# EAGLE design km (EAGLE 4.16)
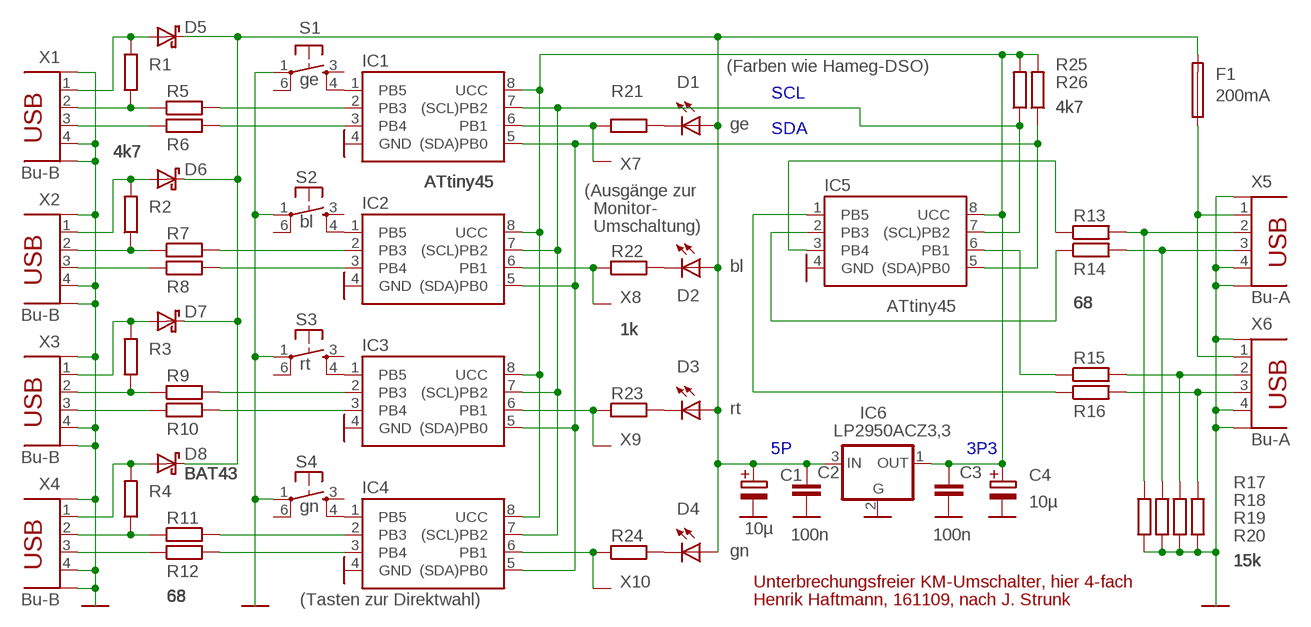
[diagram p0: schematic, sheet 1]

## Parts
C1  10µ  EE2,5-5  [E2,5-5]
C2  100n  C0805  [0805]
C3  100n  C0805  [0805]
C4  10µ  EE2,5-5  [E2,5-5]
D1  ge  LED3MM  [LED3MM]
D2  bl  LED3MM  [LED3MM]
D3  rt  LED3MM  [LED3MM]
D4  gn  LED3MM  [LED3MM]
D5  BAT43  DS  [MINIMELF]
D6  BAT43  DS  [MINIMELF]
D7  BAT43  DS  [MINIMELF]
D8  BAT43  DS  [MINIMELF]
F1  200mA  FUSE  [TE5]
IC1  ATtiny45  TN45P  [DIL08]
IC2  ATtiny45  TN45P  [DIL08]
IC3  ATtiny45  TN45P  [DIL08]
IC4  ATtiny45  TN45P  [DIL08]
IC5  ATtiny45  TN45P  [DIL08]
IC6  LP2950ACZ3,3  [TO92]
R1  4k7  R1206  [1206]
R2  4k7  R1206  [1206]
R3  4k7  R1206  [1206]
R4  4k7  R1206  [1206]
R5  68  R0805  [0805]
R6  68  R0805  [0805]
R7  68  R0805  [0805]
R8  68  R0805  [0805]
R9  68  R0805  [0805]
R10  68  R0805  [0805]
R11  68  R0805  [0805]
R12  68  R0805  [0805]
R13  68  R0805  [0805]
R14  68  R0805  [0805]
R15  68  R0805  [0805]
R16  68  R0805  [0805]
R17  15k  R0805  [0805]
R18  15k  R0805  [0805]
R19  15k  R0805  [0805]
R20  15k  R0805  [0805]
R21  1k  R0805  [0805]
R22  1k  R0805  [0805]
R23  1k  R0805  [0805]
R24  1k  R0805  [0805]
R25  4k7  R0805  [0805]
R26  4k7  R0805  [0805]
S1  ge  TASTER  [TME1]
S2  bl  TASTER  [TME1]
S3  rt  TASTER  [TME1]
S4  gn  TASTER  [TME1]
X1  Bu-B  USBB  [USBB]
X2  Bu-B  USBB  [USBB]
X3  Bu-B  USBB  [USBB]
X4  Bu-B  USBB  [USBB]
X5  Bu-A  USBA  [USBA]
X6  Bu-A  USBA  [USBA]
X7  PAD  [SMD-2MM]
X8  PAD  [SMD-2MM]
X9  PAD  [SMD-2MM]
X10  PAD  [SMD-2MM]

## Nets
3P3: C3.1 C4.+ IC1.8(UCC) IC2.8(UCC) IC3.8(UCC) IC4.8(UCC) IC5.8(UCC) IC6.1(OUT) R25.2 R26.2
5P: C1.+ C2.1 D1.A D2.A D3.A D4.A D5.K D6.K D7.K D8.K F1.2 IC6.3(IN)
5P1: D5.A R1.2 X1.1(UCC)
5P2: D6.A R2.2 X2.1(UCC)
5P3: D7.A R3.2 X3.1(UCC)
5P4: D8.A R4.2 X4.1(UCC)
5PF: F1.1 X5.1(UCC) X6.1(UCC)
GND: C1.- C2.2 C3.2 C4.- IC1.4(GND) IC2.4(GND) IC3.4(GND) IC4.4(GND) IC5.4(GND) IC6.2(GND) R17.1 R18.1 R19.1 R20.1 S1.1(P) S2.1(P) S3.1(P) S4.1(P) X1.4(GND) X1.S1(S) X1.S2(S) X2.4(GND) X2.S1(S) X2.S2(S) X3.4(GND) X3.S1(S) X3.S2(S) X4.4(GND) X4.S1(S) X4.S2(S) X5.4(GND) X5.S1(S) X5.S2(S) X6.4(GND) X6.S1(S) X6.S2(S)
N$1: D1.K R21.2
N$2: IC1.1(PB5) S1.4(S)
N$3: D2.K R22.2
N$4: D3.K R23.2
N$5: D4.K R24.2
N$6: IC2.1(PB5) S2.4(S)
N$7: IC3.1(PB5) S3.4(S)
N$8: IC4.1(PB5) S4.4(S)
N$9: R1.1 R5.1 X1.2(D-)
N$10: R6.1 X1.3(D+)
N$11: R2.1 R7.1 X2.2(D-)
N$12: IC5.3(PB4) R13.1
N$13: R8.1 X2.3(D+)
N$14: IC5.2(PB3) R14.1
N$15: IC1.2(PB3) R5.2
N$16: R3.1 R9.1 X3.2(D-)
N$17: R10.1 X3.3(D+)
N$19: R4.1 R11.1 X4.2(D-)
N$20: R12.1 X4.3(D+)
N$21: IC4.2(PB3) R11.2
N$22: IC4.3(PB4) R12.2
N$23: IC3.3(PB4) R10.2
N$24: IC1.3(PB4) R6.2
N$25: IC2.2(PB3) R7.2
N$26: IC2.3(PB4) R8.2
N$27: IC3.2(PB3) R9.2
N$29: IC1.6(PB1) R21.1 X7.1
N$30: IC2.6(PB1) R22.1 X8.1
N$31: IC3.6(PB1) R23.1 X9.1
N$32: IC4.6(PB1) R24.1 X10.1
N$33: R13.2 R17.2 X5.2(D-)
N$34: R14.2 R18.2 X5.3(D+)
N$35: R15.2 R19.2 X6.2(D-)
N$36: R16.2 R20.2 X6.3(D+)
N$37: IC5.1(PB5) R16.1
N$38: IC5.6(PB1) R15.1
SCL: IC1.7((SCL)PB2) IC2.7((SCL)PB2) IC3.7((SCL)PB2) IC4.7((SCL)PB2) IC5.7((SCL)PB2) R25.1
SDA: IC1.5((SDA)PB0) IC2.5((SDA)PB0) IC3.5((SDA)PB0) IC4.5((SDA)PB0) IC5.5((SDA)PB0) R26.1
Unconnected: S1.3(S) S1.6(P) S2.3(S) S2.6(P) S3.3(S) S3.6(P) S4.3(S) S4.6(P)

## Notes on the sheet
- (Farben wie Hameg-DSO)
- (Ausgänge zur
- Monitor-
- Umschaltung)
- Unterbrechungsfreier KM-Umschalter, hier 4-fach
- (Tasten zur Direktwahl) | Henrik Haftmann, 161109, nach J. Strunk

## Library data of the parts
C1 C4 = km:E: Elektrolytkondensator, gepolt
C2 C3 = km:C: Kondensator
D1-D4 = km:LED: Leuchtdiode
D5-D8 = km:DS: Schottky-Diode
F1 = km:FUSE: Sicherung
IC1-IC5 = km:TN*5: 8-bit-Mikrocontroller 2/4/8 KByte Flash (selbstprogrammierbar) 128/256/512 Byte RAM 128/256/512 Byte EEPROM 4x ADC, 4x PWM (8 Bit), Totzeitgenerator, 1x USI (SPI oder I²C)
IC6 = km:LP2950*: Längsregler 100 mA Low-Drop feste Ausgangsspannungen pnp-Transistor Querstrom 120 µA (bei 100 µA), 12 mA (bei 100 mA), daher für USB-Schlafmodus geeignet Bastelfreundliches TO92-Gehäuse sowie diverse SMD-Gehäuse Reichelt-Preis 0,33 &euro;
R1-R26 = km:R: Widerstand
S1-S4 = km:TASTER: Taster mit frei gelassenen Erdanschlüssen
X1-X6 = km:USB: USB-Anschluss Buchse A oder B, mit Schirm
X7-X10 = km:PAD: Anschlussfeld

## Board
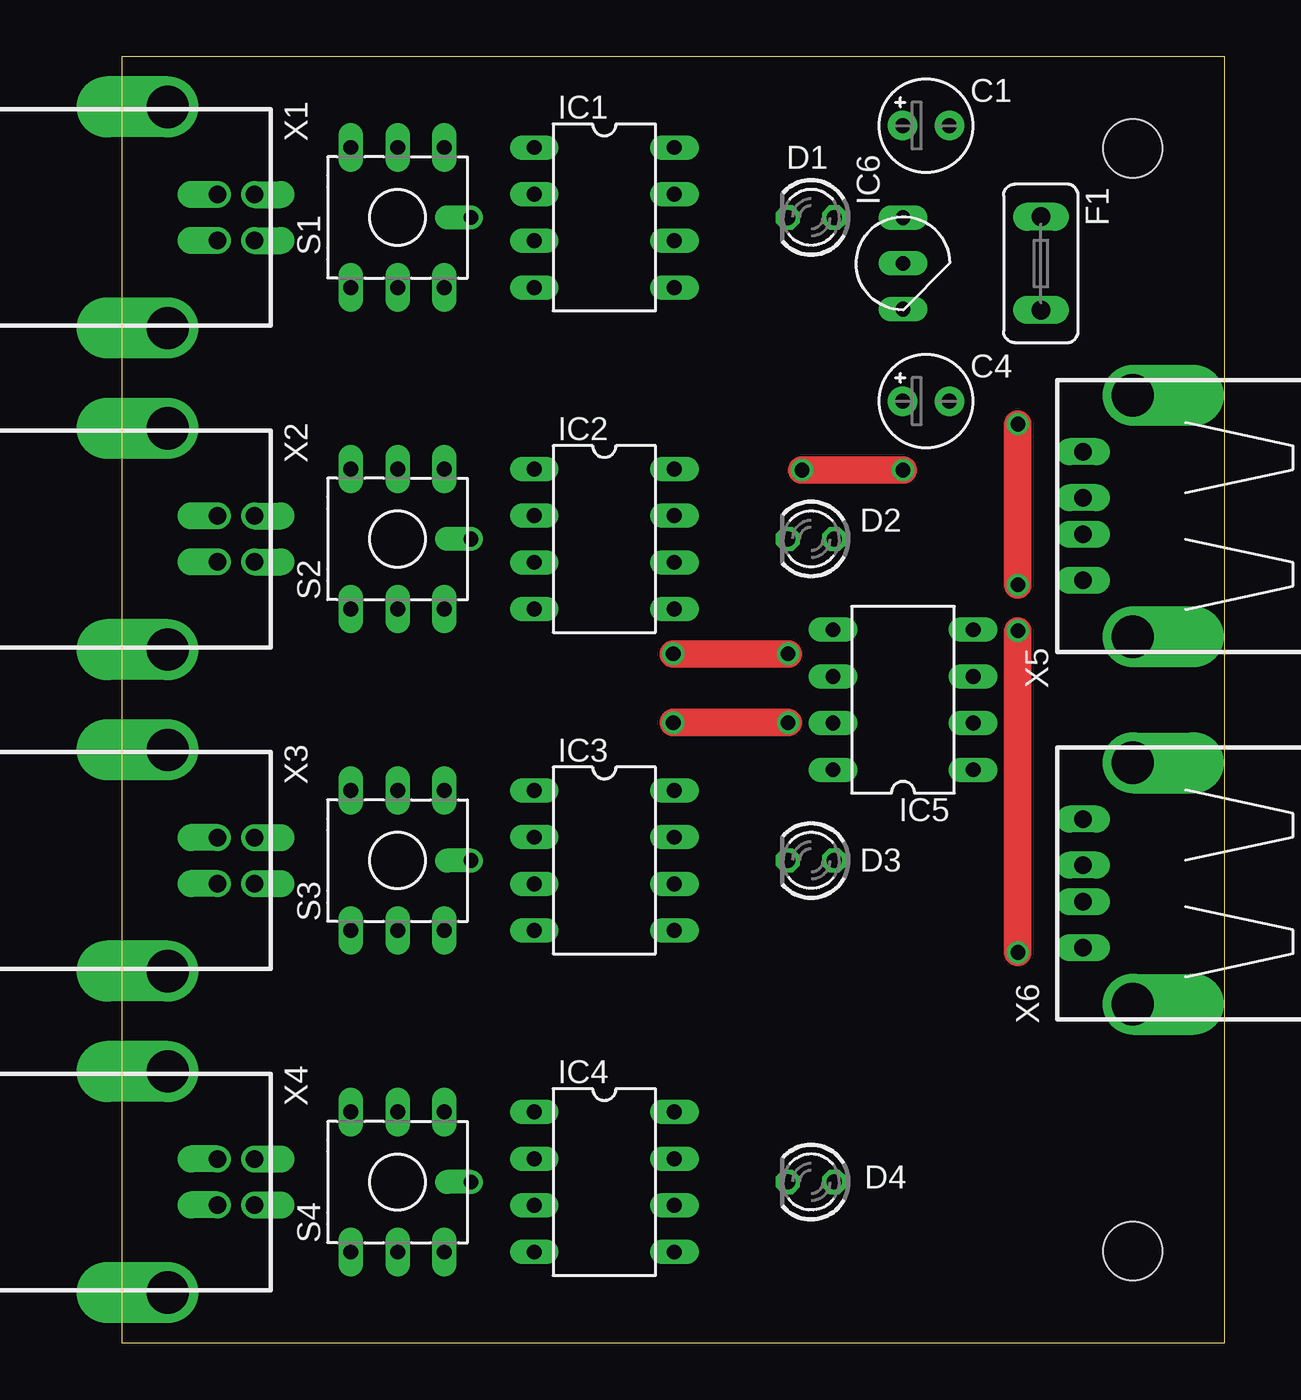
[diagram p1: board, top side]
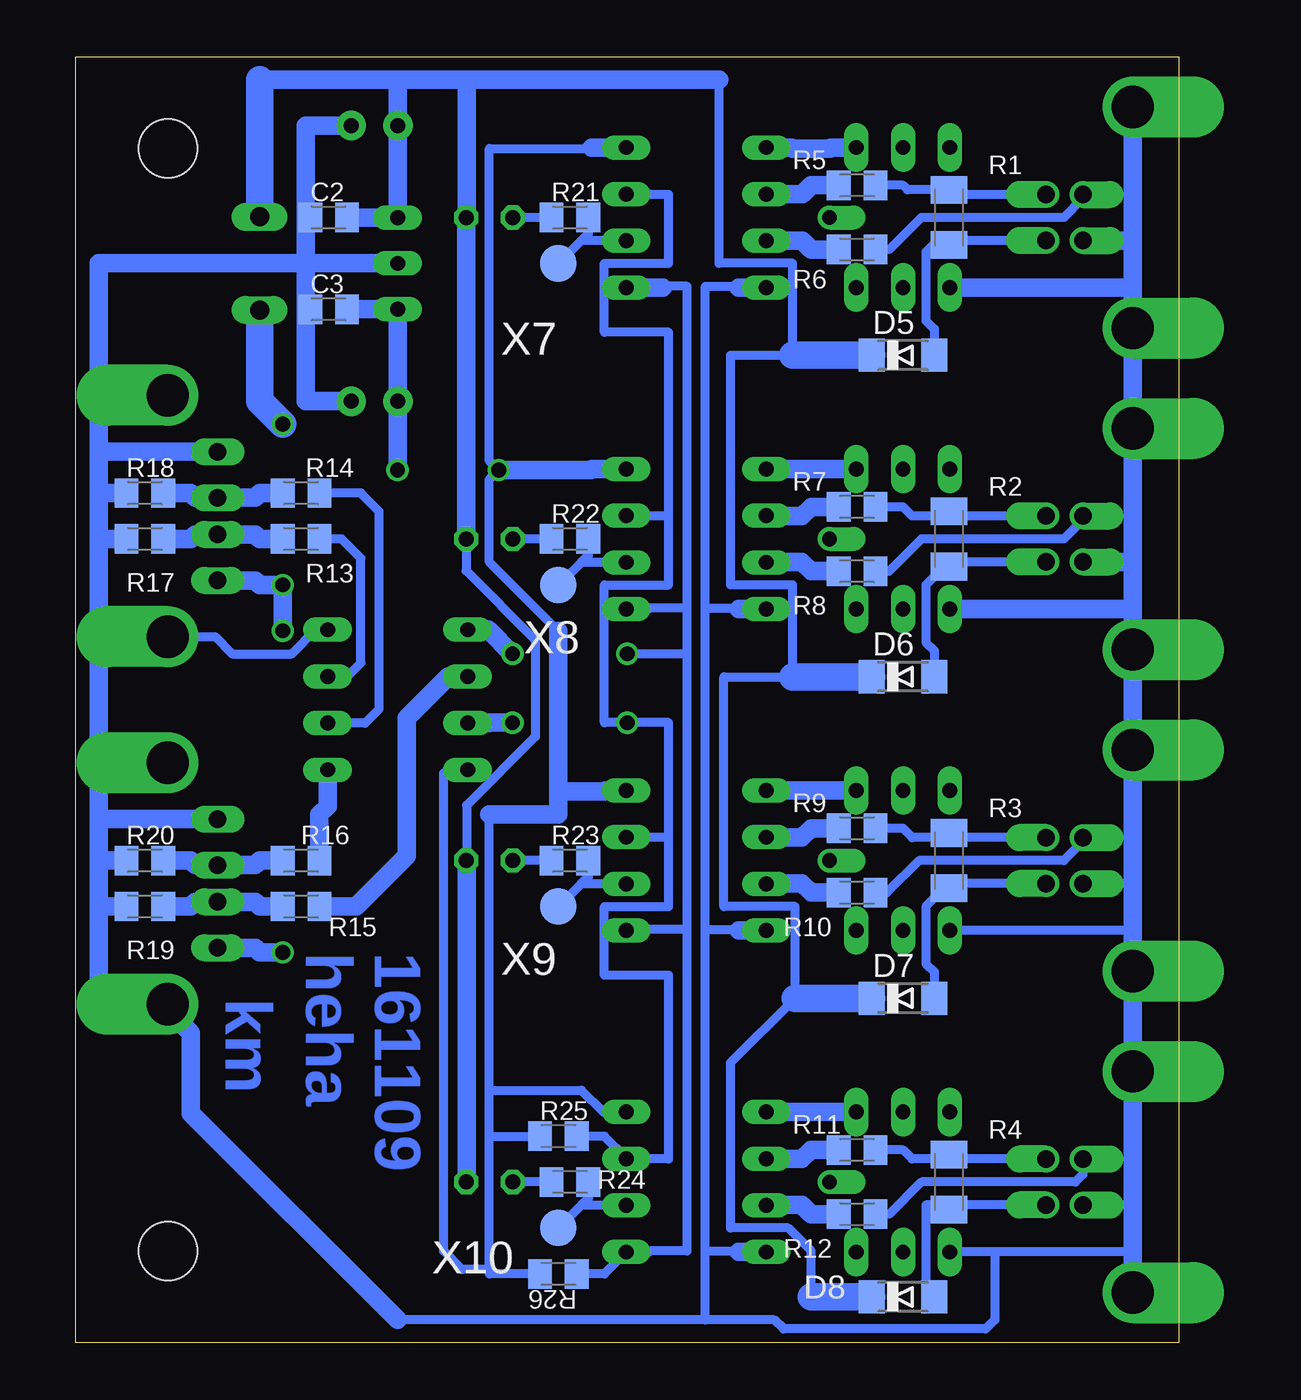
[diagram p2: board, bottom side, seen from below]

Size 60 x 70 mm. Coordinates in mm from the lower left corner, seen from the top.
Outline: 0,0 60,0 60,70 0,70 0,0
Copper layers (1+16): Top 0.035mm / dielectric 1.5mm / Bottom 0.035mm
Design rules "default": minimum track width 10mil, minimum drill 24mil, track to track 8mil, track to pad 8mil, pad to pad 8mil, via to via 8mil, smd to smd 8mil, copper to edge 10mil, drill to drill 8mil, minimum pad ring 10mil, minimum via ring 8mil, stop-mask expansion 4mil, vias tented up to drill 0mil, thermal gap 10mil
Holes 3.2 mm at 55,65 55,5

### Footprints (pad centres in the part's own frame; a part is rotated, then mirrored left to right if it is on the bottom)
E2,5-5 = drill 0.813 pad 1.6 round: + -1.27,0; - 1.27,0
0805 = smd 1.3 x 1.6: 1 -1,0; 2 1,0
LED3MM = drill 0.813 octagon: A -1.27,0; K 1.27,0
MINIMELF = smd 1.4 x 1.8: A 1.7,0; K -1.7,0
TE5 = drill 1.016 long: 1 -2.54,0; 2 2.54,0
DIL08 = drill 0.813 long: 1 -3.81,-3.81; 2 -1.27,-3.81; 3 1.27,-3.81; 4 3.81,-3.81; 5 3.81,3.81; 6 1.27,3.81; 7 -1.27,3.81; 8 -3.81,3.81
TO92 = drill 0.813 long: 1 -2.5,0; 2 0,0; 3 2.5,0
1206 = smd 1.5 x 2: 1 -1.5,0; 2 1.5,0
TME1 = drill 0.813 long: 1 -2.54,-3.81; 2 0,-3.81; 3 2.54,-3.81; 4 2.54,3.81; 5 0,3.81; 6 -2.54,3.81 | drill 0.8 offset: S 4,0
USBB = drill 0.95 offset: 1 1.25,4.71; 2 -1.25,4.71; 3 -1.25,2.71; 4 1.25,2.71 | drill 2.3 offset: S1 -6.02,0; S2 6.02,0
USBA = drill 0.95 long: 1 -3.5,2.71; 2 -1,2.71; 3 1,2.71; 4 3.5,2.71 | drill 2.3 offset: S1 -6.57,0; S2 6.57,0
SMD-2MM = smd 2 x 2: 1 0,0

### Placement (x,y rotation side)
C1  43.75,66.25 0 top
C2  46.25,61.25 180 bottom
C3  46.25,56.25 180 bottom
C4  43.75,51.25 0 top
D1  37.5,61.25 180 top
D2  37.5,43.75 180 top
D3  37.5,26.25 180 top
D4  37.5,8.75 180 top
D5  15,53.75 0 bottom
D6  15,36.25 0 bottom
D7  15,18.75 0 bottom
D8  15,2.5 0 bottom
F1  50,58.75 90 top
IC1  26.25,61.25 270 top
IC2  26.25,43.75 270 top
IC3  26.25,26.25 270 top
IC4  26.25,8.75 270 top
IC5  42.5,35 90 top
IC6  42.5,58.75 90 top
R1  12.5,61.25 270 bottom
R2  12.5,43.75 270 bottom
R3  12.5,26.25 270 bottom
R4  12.5,8.75 270 bottom
R5  17.5,63 180 bottom
R6  17.5,59.5 180 bottom
R7  17.5,45.5 180 bottom
R8  17.5,42 180 bottom
R9  17.5,28 180 bottom
R10  17.5,24.5 180 bottom
R11  17.5,10.5 180 bottom
R12  17.5,7 180 bottom
R13  47.75,43.75 180 bottom
R14  47.75,46.25 180 bottom
R15  47.75,23.75 180 bottom
R16  47.75,26.25 180 bottom
R17  56.25,43.75 0 bottom
R18  56.25,46.25 0 bottom
R19  56.25,23.75 0 bottom
R20  56.25,26.25 0 bottom
R21  33.12,61.25 180 bottom
R22  33.12,43.75 180 bottom
R23  33.12,26.25 180 bottom
R24  33.12,8.75 180 bottom
R25  33.75,11.25 180 bottom
R26  33.75,3.75 180 bottom
S1  15,61.25 0 top
S2  15,43.75 0 top
S3  15,26.25 0 top
S4  15,8.75 0 top
X1  2.5,61.25 270 top
X2  2.5,43.75 270 top
X3  2.5,26.25 270 top
X4  2.5,8.75 270 top
X5  55,45 90 top
X6  55,25 90 top
X7  33.75,58.75 0 bottom
X8  33.75,41.25 0 bottom
X9  33.75,23.75 0 bottom
X10  33.75,6.25 0 bottom

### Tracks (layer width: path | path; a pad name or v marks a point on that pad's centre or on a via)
3P3  (via drill 0.8 pad 0.8)
  Top 1.5: v37,47.5 v42.5,47.5
  Bottom 0.5: 33.75,38.75 37.5,42.5 37.5,47 v37,47.5 37.5,48 37.5,65 32,65 31.94,65.06 | R26.2 37.5,3.75 37.5,4 | 37.5,4 37.5,11.25 | 42.5,51.25 C4.+ | IC5.8 39.81,31.19 40,31 40,5 39,4 37.5,4 | 32,47.5 31.94,47.56 | 37.5,11.25 37.5,13.75 | 37.5,13.75 37.5,28.75 | IC4.8 31.31,12.56 32.5,13.75 37.5,13.75 | 37.5,11.25 R25.2 | 31.25,30 31.19,30.06
  Bottom 1: C3.1 IC6.1 42.5,51.25 v42.5,47.5 | 31.94,47.56 IC2.8 | v37,47.5 32,47.5 | 31.94,65.06 IC1.8 | 31.19,30.06 IC3.8 | 33.75,30 31.25,30 | 33.75,30 33.75,38.75 | 37.5,28.75 33.75,28.75 33.75,30
5P
  Bottom 0.5: 20,2.5 20,5 21.25,6.25 24.38,6.25 24.38,15.25 20.88,18.75 20.88,23.75 24.75,23.75 24.75,36.25 21,36.25 21,41.25 24.38,41.25 24.38,53.75 21,53.75 21,58.75 25,58.75 25,68.75 | F1.2 50,61.25 | 42.5,66.25 C1.+ | 38.75,8.75 D4.A | 38.75,61.25 D1.A | 38.77,43.77 38.75,43.75 D2.A 38.77,42.02 35,38.25 35,33 38.75,29.25 38.75,26.25 D3.A
  Bottom 1: 42.5,68.75 42.5,66.25 IC6.3 C2.1 | 42.5,68.75 50,68.75 | 25,68.75 38.75,68.75 | 38.75,68.75 42.5,68.75 | 38.75,26.25 38.75,8.75 | 38.75,68.75 38.75,61.25 | D1.A 38.77,43.77
  Bottom 1.5: D8.K 20,2.5 | 20.88,18.75 D7.K | 21,36.25 D6.K | 21,53.75 D5.K | 50,68.75 F1.2
5P1
  Bottom 0.5: X1.1 12.5,60 | D5.A 13.3,55.17 13.75,55.62 13.75,59.38 13.12,60 12.5,60 | 12.5,60 R1.2
5P2
  Bottom 0.5: D6.A 13.3,37.67 13.75,38.12 13.75,41.25 12.5,42.5 | 12.5,42.5 R2.2 | X2.1 12.5,42.5
5P3
  Bottom 0.5: X3.1 12.5,25 | D7.A 13.3,20.18 13.75,20.62 13.75,23.75 12.5,25 | 12.5,25 R3.2
5P4
  Bottom 0.5: X4.1 12.5,7.5 | D8.A 13.75,2.5 13.75,7.5 12.5,7.5 | 12.5,7.5 R4.2
5PF  (via drill 0.8, 0.8 pad 0.8)
  Top 1.5: v48.75,21.25 v48.75,38.75 | v48.75,41.25 v48.75,50
  Bottom 1: X5.1 50.25,41.5 50,41.25 v48.75,41.25 v48.75,38.75 | X6.1 50.25,21.5 50,21.25 v48.75,21.25
  Bottom 1.5: F1.1 50,51.25 v48.75,50
GND
  Bottom 0.5: 2.5,50 X2.S1 | 2.5,32.5 X3.S1 | 2.5,25 X3.4 | 2.5,15 X4.S1 | 2.5,7.5 X4.4 | 10,4.94 2.5,4.94 2.5,5 | 10,4.94 S4.1 | S3.1 2.5,22.44 2.5,22.5 | 10,4.94 10,1.25 10.5,0.75 21.5,0.75 22,1.25 25.75,1.25 | 25.75,22.5 25.75,40 | 58.75,51.25 58.75,51.57 | 58.75,28.12 58.75,28.5 | 58.75,48.12 58.75,48.5 | 25.75,1.25 25.75,5 | 2.5,40 2.5,39.94 | 2.5,57.5 2.5,57.44 | 47.5,61.25 C2.2 | 47.5,56.25 C3.2 | 25.75,1.25 42.5,1.25 | 55,18.12 X6.S1 | IC5.4 46.94,38.81 48.25,37.5 51.5,37.5 52.43,38.43 X5.S1 | 23.94,57.44 24,57.5 25.75,57.5 25.75,40 | 23.94,39.94 24,40 25.75,40 | 23.94,22.44 24,22.5 25.75,22.5 | 25.75,5 25.75,22.5 | 23.94,4.94 24,5 25.75,5
  Bottom 1: 2.5,60 2.5,57.5 X1.S2 2.5,50 2.5,42.5 | 2.5,60 X1.S1 | 2.5,60 X1.4 | 2.5,42.5 X2.4 | 2.5,42.5 2.5,40 X2.S2 2.5,32.5 2.5,25 2.5,22.5 X3.S2 2.5,15 2.5,7.5 2.5,5 X4.S2 | 58.75,51.57 X5.S2 | 58.75,46.25 58.75,48.12 58.75,51.25 58.75,58.75 47.5,58.75 | 58.75,38.43 X5.S1 | 58.75,38.43 58.75,43.75 | 58.75,43.75 58.75,46.25 | 58.75,31.57 X6.S2 | 58.75,31.57 58.75,38.43 | X6.S1 58.75,18.43 58.75,23.75 | 58.75,23.75 58.75,26.25 | 58.75,26.25 58.75,28.12 58.75,31.57 | 58.75,28.5 X6.4 | 58.75,48.5 X5.4 | 58.75,46.25 R18.1 | 58.75,43.75 R17.1 | 58.75,26.25 R20.1 | 58.75,23.75 R19.1 | 2.5,39.94 S2.1 | 2.5,57.44 S1.1 | C1.- 47.5,66.25 47.5,61.25 47.5,58.75 | 47.5,58.75 47.5,56.25 47.5,51.25 C4.- | 47.5,58.75 IC6.2 | 42.5,1.25 53.75,12.5 53.75,16.88 55,18.12 | 23.94,57.44 IC1.4 | 23.94,39.94 IC2.4 | 23.94,22.44 IC3.4 | 23.94,4.94 IC4.4
N$1
  Bottom 0.5: 36.25,61.25 D1.K R21.2
N$2
  Bottom 0.5: 21,65 21.06,65.06
  Bottom 1: 21.06,65.06 IC1.1 | S1.4 18.94,65.06 19,65 21,65
N$3
  Bottom 0.5: R22.2 D2.K
N$4
  Bottom 0.5: R23.2 D3.K
N$5
  Bottom 0.5: R24.2 D4.K
N$6
  Bottom 0.5: IC2.1 22.5,47.56 22.5,47.5
  Bottom 1: S2.4 22.5,47.56
N$7
  Bottom 0.5: IC3.1 22.5,30
  Bottom 1: S3.4 IC3.1
N$8
  Bottom 0.5: IC4.1 22.5,12.5
  Bottom 1: S4.4 IC4.1
N$9
  Bottom 0.5: X1.2 12.5,62.5 R1.1 14.75,62.75 15,63 R5.1
N$10
  Bottom 0.5: X1.3 5.21,62.29 6.25,61.25 14,61.25 15.75,59.5 R6.1
N$11
  Bottom 0.5: 12.5,45 14.5,45 15,45.5 R7.1 | 12.5,45 R2.1 | X2.2 12.5,45
N$12
  Bottom 0.5: IC5.3 45.23,36.27 44.5,37 44.5,42.7 45.55,43.75 R13.1
N$13
  Bottom 0.5: X2.3 5.21,44.79 6.25,43.75 14,43.75 15.75,42 R8.1
N$14
  Bottom 0.5: IC5.2 44.27,33.73 43.5,34.5 43.5,45.25 44.5,46.25 R14.1
N$15
  Bottom 1: IC1.2 20.48,62.52 20,63 R5.2
N$16
  Bottom 0.5: X3.2 12.5,27.5 | 12.5,27.5 R3.1 | 12.5,27.5 14.5,27.5 15,28 R9.1
N$17
  Bottom 0.5: X3.3 5.21,27.29 6.25,26.25 14.12,26.25 15.88,24.5 R10.1
N$19
  Bottom 0.5: X4.2 12.5,10 | 12.5,10 R4.1 | 12.5,10 14.5,10 15,10.5 R11.1
N$20
  Bottom 0.5: X4.3 5.21,9.16 5.62,8.75 14,8.75 15.75,7 R12.1
N$21
  Bottom 0.5: 22.5,10 22.48,10.02 IC4.2
  Bottom 1: R11.2 20,10.5 20.5,10 22.5,10
N$22
  Bottom 0.5: 22.5,7.5 22.48,7.48 IC4.3
  Bottom 1: R12.2 20,7 20.5,7.5 22.5,7.5
N$23
  Bottom 0.5: 22.5,25 22.48,24.98 IC3.3
  Bottom 1: R10.2 20,24.5 20.5,25 22.5,25
N$24
  Bottom 1: IC1.3 20.48,59.98 20,59.5 R6.2
N$25
  Bottom 0.5: 22.5,45 22.5,45.02 IC2.2
  Bottom 1: R7.2 20,45.5 20.5,45 22.5,45
N$26
  Bottom 0.5: 22.5,42.5 22.5,42.48 IC2.3
  Bottom 1: R8.2 20,42 20.5,42.5 22.5,42.5
N$27
  Bottom 0.5: 22.5,27.5 22.48,27.52 IC3.2
  Bottom 1: R9.2 20,28 20.5,27.5 22.5,27.5
N$29
  Bottom 0.5: IC1.6 32.5,59.98 | 32.5,59.98 32.52,59.98 X7.1 | 32.5,59.98 32.5,60 32.12,60.38 R21.1
N$30
  Bottom 0.5: IC2.6 32.5,42.48 | 32.5,42.48 32.52,42.48 X8.1 | 32.5,42.48 32.5,42.5 32.12,42.88 R22.1
N$31
  Bottom 0.5: IC3.6 32.5,24.98 | 32.5,24.98 32.52,24.98 X9.1 | 32.5,24.98 32.5,25 32.12,25.38 R23.1
N$32
  Bottom 0.5: IC4.6 32.5,7.48 | 32.5,7.48 32.52,7.48 X10.1 | 32.5,7.48 32.5,7.5 32.12,7.88 R24.1
N$33
  Bottom 1: R13.2 50,43.75 50.25,44 X5.2 53.5,44 53.75,43.75 R17.2
N$34
  Bottom 1: R14.2 50,46.25 50.25,46 X5.3 53.5,46 53.75,46.25 R18.2
N$35
  Bottom 1: R15.2 50,23.75 50.25,24 X6.2 53.5,24 53.75,23.75 R19.2
N$36
  Bottom 1: R16.2 50,26.25 50.25,26 X6.3 53.5,26 53.75,26.25 R20.2
N$37
  Bottom 1: R16.1 46.75,28.75 46.31,29.19 IC5.1
N$38
  Bottom 1: IC5.6 39.73,36.27 42,34 42,26.5 44.75,23.75 R15.1
SCL  (via drill 0.8 pad 0.8)
  Top 1.5: v30,33.75 v36.25,33.75
  Bottom 0.5: IC3.7 30.02,27.52 30,27.5 27.75,27.5 | 27.75,27.5 27.75,23.75 31.25,23.75 31.25,20 27.75,20 27.75,10 29,10 29.02,10.02 IC4.7 30.06,10.06 31.25,11.25 R25.1 | 27.75,45 27.75,55 31.25,55 31.25,58.75 27.75,58.75 27.75,62.5 28.75,62.5 28.77,62.52 IC1.7 | IC2.7 30.02,45.02 30,45 27.75,45 | 27.75,45 27.75,41.25 31.25,41.25 31.25,33.75 v30,33.75 27.75,33.75 27.75,27.5 | 37.5,33.75 37.52,33.73
  Bottom 1: 37.52,33.73 IC5.7 | v36.25,33.75 37.5,33.75
SDA  (via drill 0.8 pad 0.8)
  Top 1.5: v30,37.5 v36.25,37.5
  Bottom 0.5: 26.75,22.5 26.75,5 28.75,5 28.81,4.94 IC4.5 31.25,3.75 R26.1 | 26.75,22.5 26.75,37.5 | 26.75,37.5 26.75,40 | IC3.5 30,22.5 26.75,22.5 | IC2.5 28.81,39.94 28.75,40 26.75,40 | 26.75,37.5 v30,37.5 | 28.06,57.44 28,57.5 26.75,57.5 26.75,40
  Bottom 1: IC5.5 37.56,38.81 v36.25,37.5 | 28.06,57.44 IC1.5

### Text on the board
Bottom: 161109 | heha
Measures: 70 | 60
